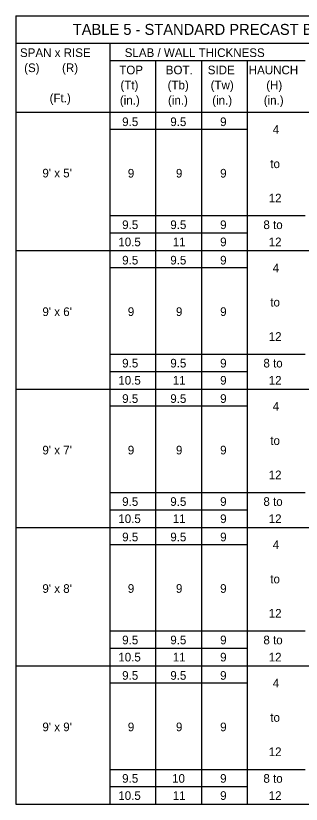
# Model space of a CAD drawing. Extents: x 10346.98 to 10349.19, y 76399.48 to 76400.59.
# Drawn here: x 10346.985 to 10347.193, y 76399.925 to 76400.5 of the extents above; entities that cross this region are included whole.
import ezdxf

# ---------------------------------------------------------------- set-up
doc = ezdxf.new("R2010")
doc.units = 0
doc.layers.add('AdhocPoint_dp', color=7, linetype='Continuous')
doc.layers.add('PlotBorder_dp', color=7, linetype='Continuous')

msp = doc.modelspace()

# ---------------------------------------------------------------- linework, layer by layer
at = {"layer": 'PlotBorder_dp'}
for p, q in [((10346.98451, 76400.49971), (10346.98451, 76399.92549)), ((10346.98451, 76400.49971), (10347.57925, 76400.49971)), ((10346.98451, 76400.47984), (10347.57925, 76400.47984)), ((10347.05314, 76400.47984), (10347.05314, 76399.92549)), ((10347.05314, 76400.46724), (10347.19559, 76400.46724)), ((10347.0865, 76400.46724), (10347.0865, 76399.92549)), ((10347.11986, 76400.46724), (10347.11986, 76399.92549)), ((10347.15323, 76400.46724), (10347.15323, 76399.92549)), ((10346.98451, 76400.42949), (10347.57925, 76400.42949)), ((10347.15323, 76400.41689), (10347.05314, 76400.41689)), ((10347.19559, 76400.35389), (10347.05314, 76400.35389)), ((10347.15323, 76400.34129), (10347.05314, 76400.34129)), ((10346.98451, 76400.32869), (10347.50186, 76400.32869)), ((10347.15323, 76400.31609), (10347.05314, 76400.31609)), ((10347.19559, 76400.25309), (10347.05314, 76400.25309)), ((10347.15323, 76400.24049), (10347.05314, 76400.24049)), ((10346.98451, 76400.22789), (10347.50186, 76400.22789)), ((10347.15323, 76400.21529), (10347.05314, 76400.21529)), ((10347.19559, 76400.15229), (10347.05314, 76400.15229)), ((10347.15323, 76400.13969), (10347.05314, 76400.13969)), ((10346.98451, 76400.12709), (10347.50186, 76400.12709)), ((10347.15323, 76400.11449), (10347.05314, 76400.11449)), ((10347.19559, 76400.05149), (10347.05314, 76400.05149)), ((10347.15323, 76400.03889), (10347.05314, 76400.03889)), ((10346.98451, 76400.02629), (10347.50186, 76400.02629)), ((10347.15323, 76400.01369), (10347.05314, 76400.01369)), ((10347.19559, 76399.95066), (10347.05314, 76399.95066)), ((10347.15323, 76399.93806), (10347.05314, 76399.93806)), ((10346.98451, 76399.92549), (10347.57925, 76399.92549))]:
    msp.add_line(p, q, dxfattribs=at)

# ---------------------------------------------------------------- texts
at = {"layer": 'AdhocPoint_dp'}
for s, height, p in [('TABLE 5 - STANDARD PRECAST BOX CULVERT DESIGNS (2" COVER) - 9\' SPANS', 0.008, (10347.02607, 76400.48578)), ('SLAB / WALL THICKNESS', 0.0063, (10347.06396, 76400.46968))]:
    msp.add_text(s, height=height, dxfattribs=at).set_placement(p)
at = {"layer": 'PlotBorder_dp'}
for s, p in [('SPAN x RISE', (10346.9876, 76400.46968)), ('(S)       (R)', (10346.99064, 76400.45868)), ('TOP', (10347.05997, 76400.45708)), ('BOT.', (10347.0939, 76400.45708)), ('SIDE', (10347.12449, 76400.45708)), ('HAUNCH', (10347.15439, 76400.45708)), ('(Tt)', (10347.06081, 76400.44608)), ('(Tb)', (10347.09524, 76400.44608)), ('(Tw)', (10347.1266, 76400.44608)), ('(H)', (10347.16713, 76400.44608)), ('(Ft.)', (10347.00921, 76400.43668)), ('(in.)', (10347.06042, 76400.43508)), ('(in.)', (10347.09551, 76400.43508)), ('(in.)', (10347.12775, 76400.43508)), ('(in.)', (10347.16532, 76400.43508)), ('9.5', (10347.0621, 76400.41937)), ('9.5', (10347.09719, 76400.41937)), ('9', (10347.13354, 76400.41937)), ('4', (10347.17189, 76400.41377)), ('to', (10347.17011, 76400.38877)), ("9' x 5'", (10347.00394, 76400.38198)), ('9', (10347.06621, 76400.38187)), ('9', (10347.1013, 76400.38187)), ('9', (10347.13354, 76400.38187)), ('12', (10347.16894, 76400.36377)), ('9.5', (10347.0621, 76400.34437)), ('9.5', (10347.09719, 76400.34437)), ('9', (10347.13354, 76400.34437)), ('8 to', (10347.16507, 76400.34437)), ('10.5', (10347.05927, 76400.33187)), ('11', (10347.09897, 76400.33187)), ('9', (10347.13354, 76400.33187)), ('12', (10347.16894, 76400.33187)), ('9.5', (10347.0621, 76400.31857)), ('9.5', (10347.09719, 76400.31857)), ('9', (10347.13354, 76400.31857)), ('4', (10347.17189, 76400.31297)), ('to', (10347.17011, 76400.28797)), ("9' x 6'", (10347.00394, 76400.28104)), ('9', (10347.06621, 76400.28107)), ('9', (10347.1013, 76400.28107)), ('9', (10347.13354, 76400.28107)), ('12', (10347.16894, 76400.26297)), ('9.5', (10347.0621, 76400.24357)), ('9.5', (10347.09719, 76400.24357)), ('9', (10347.13354, 76400.24357)), ('8 to', (10347.16507, 76400.24357)), ('10.5', (10347.05927, 76400.23107)), ('11', (10347.09897, 76400.23107)), ('9', (10347.13354, 76400.23107)), ('12', (10347.16894, 76400.23107)), ('9.5', (10347.0621, 76400.21777)), ('9.5', (10347.09719, 76400.21777)), ('9', (10347.13354, 76400.21777)), ('4', (10347.17189, 76400.21217)), ('to', (10347.17011, 76400.18717)), ("9' x 7'", (10347.00394, 76400.18026)), ('9', (10347.06621, 76400.18027)), ('9', (10347.1013, 76400.18027)), ('9', (10347.13354, 76400.18027)), ('12', (10347.16894, 76400.16217)), ('9.5', (10347.0621, 76400.14277)), ('9.5', (10347.09719, 76400.14277)), ('9', (10347.13354, 76400.14277)), ('8 to', (10347.16507, 76400.14277)), ('10.5', (10347.05927, 76400.13027)), ('11', (10347.09897, 76400.13027)), ('9', (10347.13354, 76400.13027)), ('12', (10347.16894, 76400.13027)), ('9.5', (10347.0621, 76400.11697)), ('9.5', (10347.09719, 76400.11697)), ('9', (10347.13354, 76400.11697)), ('4', (10347.17189, 76400.11137)), ('to', (10347.17011, 76400.08637)), ("9' x 8'", (10347.00394, 76400.07942)), ('9', (10347.06621, 76400.07947)), ('9', (10347.1013, 76400.07947)), ('9', (10347.13354, 76400.07947)), ('12', (10347.16894, 76400.06137)), ('9.5', (10347.0621, 76400.04197)), ('9.5', (10347.09719, 76400.04197)), ('9', (10347.13354, 76400.04197)), ('8 to', (10347.16507, 76400.04197)), ('10.5', (10347.05927, 76400.02947)), ('11', (10347.09897, 76400.02947)), ('9', (10347.13354, 76400.02947)), ('12', (10347.16894, 76400.02947)), ('9.5', (10347.0621, 76400.01614)), ('9.5', (10347.09719, 76400.01614)), ('9', (10347.13354, 76400.01614)), ('4', (10347.17189, 76400.01054)), ('to', (10347.17011, 76399.98554)), ("9' x 9'", (10347.00394, 76399.97864)), ('9', (10347.06621, 76399.97864)), ('9', (10347.1013, 76399.97864)), ('9', (10347.13354, 76399.97864)), ('12', (10347.16894, 76399.96054)), ('9.5', (10347.0621, 76399.94114)), ('10', (10347.09849, 76399.94114)), ('9', (10347.13354, 76399.94114)), ('8 to', (10347.16507, 76399.94114)), ('10.5', (10347.05927, 76399.92864)), ('11', (10347.09897, 76399.92864)), ('9', (10347.13354, 76399.92864)), ('12', (10347.16894, 76399.92864))]:
    msp.add_text(s, height=0.0063, dxfattribs=at).set_placement(p)

doc.saveas('drawing.dxf')
